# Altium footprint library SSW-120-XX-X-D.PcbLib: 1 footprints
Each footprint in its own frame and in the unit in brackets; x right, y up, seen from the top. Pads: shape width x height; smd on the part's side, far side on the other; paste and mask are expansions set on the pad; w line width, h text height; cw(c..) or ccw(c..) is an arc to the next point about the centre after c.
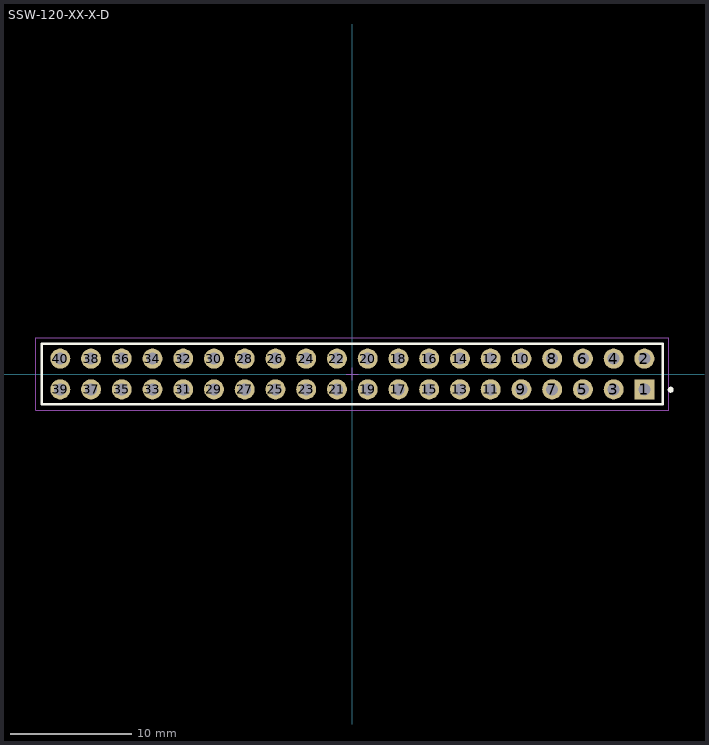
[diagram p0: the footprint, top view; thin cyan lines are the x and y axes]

## SSW-120-XX-X-D [mm] "2.54mm pitch, 40 pin, socket strip; double row"
height 8.51
pads (40):
  rect 1.65x1.65 / inner round 1.65 / far side rect 1.65x1.65 hole 1 mask+0: 1(24.13,-1.27)
  round 1.65 hole 1 mask+0: 2(24.13,1.27) 3(21.59,-1.27) 4(21.59,1.27) 5(19.05,-1.27) 6(19.05,1.27) 7(16.51,-1.27) 8(16.51,1.27) 9(13.97,-1.27) 10(13.97,1.27) 11(11.43,-1.27) 12(11.43,1.27) 13(8.89,-1.27) 14(8.89,1.27) 15(6.35,-1.27) 16(6.35,1.27) 17(3.81,-1.27) 18(3.81,1.27) 19(1.27,-1.27) 20(1.27,1.27) 21(-1.27,-1.27) 22(-1.27,1.27) 23(-3.81,-1.27) 24(-3.81,1.27) 25(-6.35,-1.27) 26(-6.35,1.27) 27(-8.89,-1.27) 28(-8.89,1.27) 29(-11.43,-1.27) 30(-11.43,1.27) 31(-13.97,-1.27) 32(-13.97,1.27) 33(-16.51,-1.27) 34(-16.51,1.27) 35(-19.05,-1.27) 36(-19.05,1.27) 37(-21.59,-1.27) 38(-21.59,1.27) 39(-24.13,-1.27) 40(-24.13,1.27)
Top Overlay:
  circle w0.25: c26.3,-1.3 r0.125
  lines w0.2: -25.65,-2.5 -25.65,2.5 25.65,2.5 25.65,-2.5 -25.65,-2.5
Mechanical 12:
  lines w0.001: -25.65,-2.5 -25.65,2.5 25.65,2.5 25.65,-2.5 -25.65,-2.5
Mechanical 13:
  lines w0.1: -25.65,-2.5 -25.65,2.5 25.65,2.5 25.65,-2.5 -25.65,-2.5
  text ".Designator" at 0,-0.127 h1.52
Mechanical 15:
  lines w0.05: -0.5,0 0.5,0 ; 0,-0.5 0,0.5 ; -26.15,-3 -26.15,3 26.15,3 26.15,-3 -26.15,-3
